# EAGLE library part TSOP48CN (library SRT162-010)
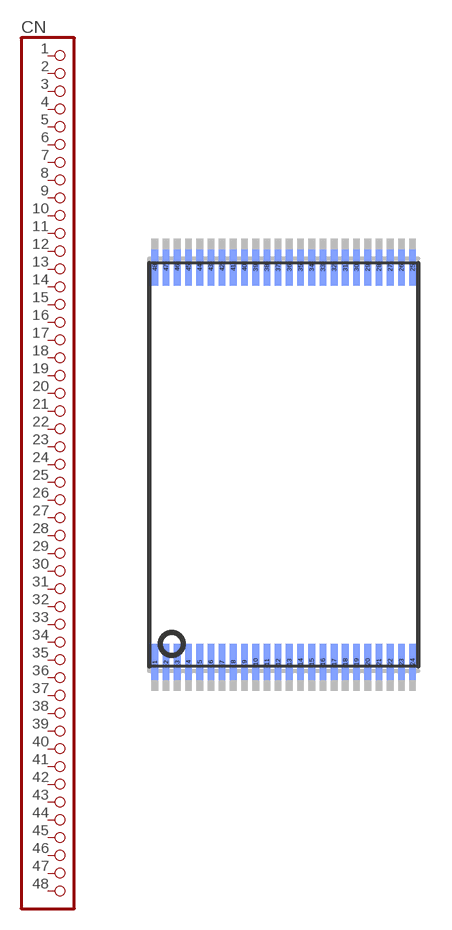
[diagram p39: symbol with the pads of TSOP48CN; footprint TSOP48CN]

Designator prefix CN

## TSOP48CN  [TSOP48CN]
1  1  pas
2  2  pas
3  3  pas
4  4  pas
5  5  pas
6  6  pas
7  7  pas
8  8  pas
9  9  pas
10  10  pas
11  11  pas
12  12  pas
13  13  pas
14  14  pas
15  15  pas
16  16  pas
17  17  pas
18  18  pas
19  19  pas
20  20  pas
21  21  pas
22  22  pas
23  23  pas
24  24  pas
25  25  pas
26  26  pas
27  27  pas
28  28  pas
29  29  pas
30  30  pas
31  31  pas
32  32  pas
33  33  pas
34  34  pas
35  35  pas
36  36  pas
37  37  pas
38  38  pas
39  39  pas
40  40  pas
41  41  pas
42  42  pas
43  43  pas
44  44  pas
45  45  pas
46  46  pas
47  47  pas
48  48  pas

## Footprint TSOP48CN (pad centres in mm)
smd 0.3 x 1.6 bottom: 1 -5.75,-8.8; 2 -5.25,-8.8; 3 -4.75,-8.8; 4 -4.25,-8.8; 5 -3.75,-8.8; 6 -3.25,-8.8; 7 -2.75,-8.8; 8 -2.25,-8.8; 9 -1.75,-8.8; 10 -1.25,-8.8; 11 -0.75,-8.8; 12 -0.25,-8.8; 13 0.25,-8.8; 14 0.75,-8.8; 15 1.25,-8.8; 16 1.75,-8.8; 17 2.25,-8.8; 18 2.75,-8.8; 19 3.25,-8.8; 20 3.75,-8.8; 21 4.25,-8.8; 22 4.75,-8.8; 23 5.25,-8.8; 24 5.75,-8.8; 25 5.75,8.8; 26 5.25,8.8; 27 4.75,8.8; 28 4.25,8.8; 29 3.75,8.8; 30 3.25,8.8; 31 2.75,8.8; 32 2.25,8.8; 33 1.75,8.8; 34 1.25,8.8; 35 0.75,8.8; 36 0.25,8.8; 37 -0.25,8.8; 38 -0.75,8.8; 39 -1.25,8.8; 40 -1.75,8.8; 41 -2.25,8.8; 42 -2.75,8.8; 43 -3.25,8.8; 44 -3.75,8.8; 45 -4.25,8.8; 46 -4.75,8.8; 47 -5.25,8.8; 48 -5.75,8.8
